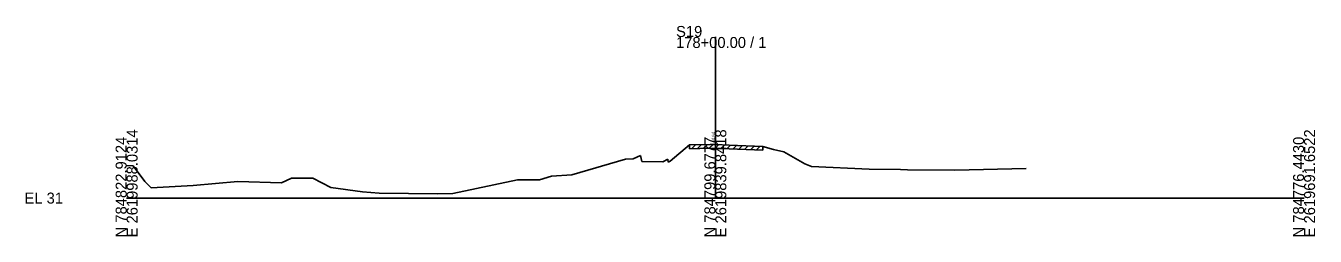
# Model space of a CAD drawing. Extents: x -26 to 1603, y -10 to 5028.
# Drawn here: x -25.7 to 302.8, y 2990.3 to 3043.8 of the extents above; entities that cross this region are included whole.
import ezdxf

# ---------------------------------------------------------------- set-up
doc = ezdxf.new("R2010")
doc.units = 0
for name, color, linetype in [('RD_GPK_XS_Cell', 7, 'Continuous'), ('RD_XS_ExGround', 7, 'Continuous'), ('RD_XS_ExPaveRet', 7, 'Continuous'), ('RD_XS_TX_Elev_EX', 7, 'Continuous')]:
    doc.layers.add(name, color=color, linetype=linetype)

msp = doc.modelspace()

# ---------------------------------------------------------------- linework, layer by layer
at = {"layer": 'RD_GPK_XS_Cell'}
for p, q in [((150, 3000), (150, 3040.99)), ((0, 3000), (150, 3000)), ((150, 3000), (300, 3000))]:
    msp.add_line(p, q, dxfattribs=at)
at = {"layer": 'RD_XS_ExGround'}
for p, q in [((138.49, 3009.41), (143.4, 3013.52)), ((143.4, 3013.52), (148.68, 3013.66)), ((148.68, 3013.66), (150.06, 3013.64)), ((150.06, 3013.64), (153.53, 3013.5)), ((153.53, 3013.5), (162.13, 3013.16)), ((162.13, 3013.16), (164.84, 3012.33)), ((113.44, 3005.95), (127.1, 3009.94)), ((127.1, 3009.94), (129.07, 3009.99)), ((129.07, 3009.99), (130.94, 3010.87)), ((130.94, 3010.87), (131.3, 3009.27)), ((136.6, 3009.19), (137.93, 3009.9)), ((137.93, 3009.9), (137.94, 3009.16)), ((137.94, 3009.16), (138.49, 3009.41)), ((164.84, 3012.33), (167.43, 3011.76)), ((167.43, 3011.76), (172.76, 3008.71)), ((0, 3008.26), (1.64, 3008.2)), ((1.64, 3008.2), (4.64, 3004.26)), ((131.3, 3009.27), (136.6, 3009.19)), ((172.76, 3008.71), (174.53, 3008)), ((174.53, 3008), (189.15, 3007.37)), ((189.15, 3007.37), (197.17, 3007.25)), ((197.17, 3007.25), (198.95, 3007.18)), ((198.95, 3007.18), (210.99, 3007.14)), ((210.99, 3007.14), (229.16, 3007.51)), ((4.64, 3004.26), (6.25, 3002.6)), ((6.25, 3002.6), (16.97, 3003.2)), ((16.97, 3003.2), (28.37, 3004.26)), ((28.37, 3004.26), (39.46, 3003.88)), ((39.46, 3003.88), (41.99, 3005.11)), ((41.99, 3005.11), (47.42, 3005.03)), ((47.42, 3005.03), (52.07, 3002.66)), ((83.1, 3001.16), (99.62, 3004.63)), ((99.62, 3004.63), (105.2, 3004.62)), ((105.2, 3004.62), (108.27, 3005.56)), ((108.27, 3005.56), (113.44, 3005.95)), ((52.07, 3002.66), (60.12, 3001.57)), ((60.12, 3001.57), (64.31, 3001.26)), ((64.31, 3001.26), (79.33, 3001.05)), ((79.33, 3001.05), (83.1, 3001.16))]:
    msp.add_line(p, q, dxfattribs=at)
at = {"layer": 'RD_XS_ExPaveRet'}
for p, q in [((143.4, 3013.52), (143.4, 3012.52)), ((143.4, 3012.52), (148.68, 3012.66)), ((143.93, 3012.54), (144.96, 3013.56)), ((145.43, 3012.58), (146.46, 3013.6)), ((146.93, 3012.62), (147.96, 3013.64)), ((148.43, 3012.66), (149.42, 3013.65)), ((148.68, 3012.66), (150.06, 3012.64)), ((149.93, 3012.64), (150.89, 3013.6)), ((151.43, 3012.58), (152.39, 3013.54)), ((152.93, 3012.52), (153.89, 3013.48)), ((154.43, 3012.46), (155.39, 3013.42)), ((155.93, 3012.4), (156.89, 3013.36)), ((157.43, 3012.34), (158.39, 3013.3)), ((158.93, 3012.28), (159.89, 3013.24)), ((160.43, 3012.22), (161.39, 3013.18)), ((162.13, 3013.16), (162.13, 3012.16)), ((150.06, 3012.64), (153.53, 3012.5)), ((153.53, 3012.5), (162.13, 3012.16))]:
    msp.add_line(p, q, dxfattribs=at)

# ---------------------------------------------------------------- texts
at = {"layer": 'RD_GPK_XS_Cell'}
for s, p in [('S19', (140, 3040.99)), ('178+00.00 / 1', (140, 3038.19)), ('EL 31', (-26, 2998.6))]:
    msp.add_text(s, height=2.8, dxfattribs=at).set_placement(p)
for s, p in [('E 2619988.0314', (2.8, 2990)), ('E 2619839.8418', (152.8, 2990)), ('E 2619691.6522', (302.8, 2990)), ('N 784822.9124', (0, 2990)), ('N 784799.6777', (150, 2990)), ('N 784776.4430', (300, 2990))]:
    msp.add_text(s, height=2.8, rotation=90, dxfattribs=at).set_placement(p)
at = {"layer": 'RD_XS_TX_Elev_EX'}
msp.add_text('44.64', height=0.8, rotation=90, dxfattribs=at).set_placement((149.9, 3014.08))

doc.saveas('drawing.dxf')
